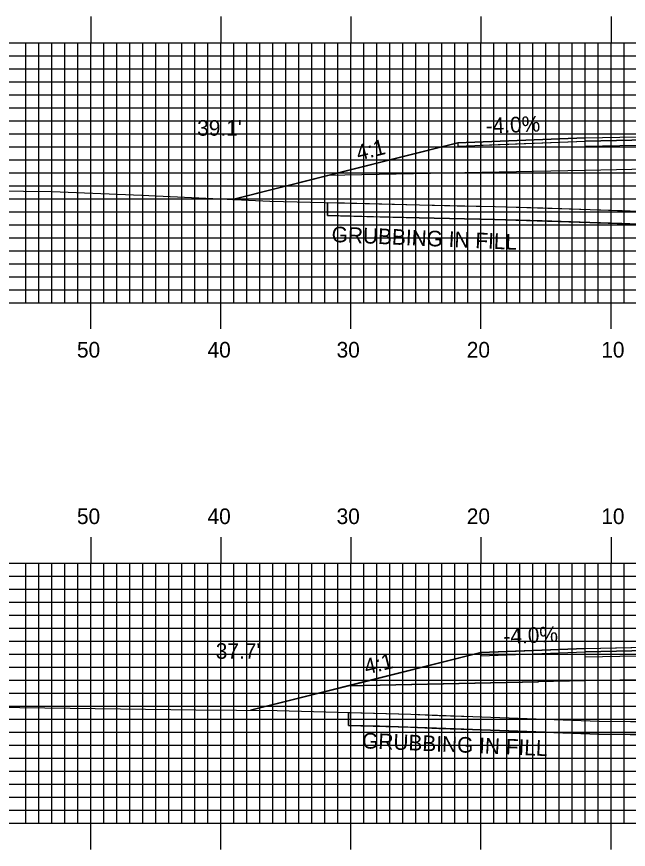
# Model space of a CAD drawing. Extents: x 1773203 to 1773546, y 442591 to 442811.
# Drawn here: x 1773312.9 to 1773360, y 442646.7 to 442710.7 of the extents above; entities that cross this region are included whole.
import ezdxf

# ---------------------------------------------------------------- set-up
doc = ezdxf.new("R2010")
doc.units = 0
for name, color, linetype in [('ANNOTATION', 7, 'Continuous'), ('D_Drainage_Culvert', 7, 'Continuous'), ('D_Roadway_Centerline', 7, 'Continuous'), ('D_Roadway_Edge_Shoulder', 7, 'Continuous'), ('D_Roadway_Edge_TW', 7, 'Continuous'), ('D_Roadway_Pavement', 7, 'Continuous'), ('D_Roadway_SlopeLines', 7, 'Continuous'), ('D_Roadway_SubGrade', 7, 'Continuous'), ('D_Text_Standard', 7, 'Continuous'), ('GRUBBING IN FILL', 7, 'Continuous'), ('H_V ANNOTATION', 7, 'Continuous'), ('MAJOR', 7, 'Continuous'), ('MINOR', 7, 'Continuous'), ('S_Roadway_Centerline', 7, 'Continuous')]:
    doc.layers.add(name, color=color, linetype=linetype)

msp = doc.modelspace()

# ---------------------------------------------------------------- linework, layer by layer
at = {"layer": 'D_Drainage_Culvert'}
for p, q in [((1773356.633, 442701.354), (1773346.862, 442700.963)), ((1773356.633, 442662.104), (1773348.633, 442661.784))]:
    msp.add_line(p, q, dxfattribs=at)
for points in [[(1773346.862, 442700.963), (1773342.862, 442699.963), (1773329.514, 442696.626)], [(1773348.633, 442661.784), (1773344.633, 442660.784), (1773330.914, 442657.355)]]:
    msp.add_lwpolyline(points, dxfattribs=at)
at = {"layer": 'D_Roadway_Centerline'}
for points in [[(1773329.514, 442696.626), (1773346.862, 442700.963), (1773356.633, 442701.354), (1773368.633, 442701.594), (1773380.633, 442701.354), (1773388.632, 442701.034), (1773388.632, 442701.034), (1773412.135, 442695.159)], [(1773330.914, 442657.355), (1773338.457, 442659.24), (1773348.633, 442661.784), (1773348.633, 442661.784), (1773348.633, 442661.784), (1773352.008, 442661.919), (1773356.633, 442662.104), (1773363.648, 442662.245), (1773368.633, 442662.344), (1773380.633, 442662.104), (1773388.632, 442661.784), (1773388.632, 442661.784), (1773412.369, 442655.85)]]:
    msp.add_lwpolyline(points, dxfattribs=at)
at = {"layer": 'D_Roadway_Edge_Shoulder'}
for points in [[(1773356.633, 442701.354), (1773348.633, 442701.034), (1773348.633, 442700.784), (1773356.633, 442701.104)], [(1773356.633, 442662.104), (1773348.633, 442661.784), (1773348.633, 442661.534), (1773356.633, 442661.854)]]:
    msp.add_lwpolyline(points, close=True, dxfattribs=at)
at = {"layer": 'D_Roadway_Edge_TW'}
for points in [[(1773356.633, 442701.104), (1773356.633, 442701.354), (1773368.633, 442701.594), (1773380.633, 442701.354), (1773380.633, 442701.104), (1773368.633, 442701.344)], [(1773356.633, 442661.854), (1773356.633, 442662.104), (1773368.633, 442662.344), (1773380.633, 442662.104), (1773380.633, 442661.854), (1773368.633, 442662.094)]]:
    msp.add_lwpolyline(points, close=True, dxfattribs=at)
at = {"layer": 'D_Roadway_Pavement'}
for points in [[(1773356.633, 442700.687), (1773356.633, 442701.104), (1773368.633, 442701.344), (1773380.633, 442701.104), (1773380.633, 442700.687), (1773368.633, 442700.927)], [(1773356.633, 442661.437), (1773356.633, 442661.854), (1773368.633, 442662.094), (1773380.633, 442661.854), (1773380.633, 442661.437), (1773368.633, 442661.677)]]:
    msp.add_lwpolyline(points, close=True, dxfattribs=at)
at = {"layer": 'D_Roadway_SlopeLines'}
msp.add_lwpolyline([(1773338.457, 442659.24), (1773353.069, 442659.533), (1773338.457, 442659.24), (1773332.659, 442657.791)], dxfattribs=at)
at = {"layer": 'D_Roadway_SubGrade'}
for points in [[(1773356.633, 442698.854), (1773336.84, 442698.458), (1773346.862, 442700.963), (1773346.862, 442700.713), (1773356.633, 442701.104), (1773368.633, 442701.344), (1773380.633, 442701.104), (1773388.632, 442700.784), (1773388.632, 442700.784), (1773388.632, 442701.034), (1773398.808, 442698.49), (1773380.633, 442698.854), (1773368.633, 442699.094)], [(1773356.633, 442659.604), (1773338.457, 442659.24), (1773348.633, 442661.784), (1773348.633, 442661.534), (1773356.633, 442661.854), (1773368.633, 442662.094), (1773380.633, 442661.854), (1773388.633, 442661.534), (1773388.632, 442661.784), (1773398.809, 442659.24), (1773380.633, 442659.604), (1773368.633, 442659.844)]]:
    msp.add_lwpolyline(points, close=True, dxfattribs=at)
at = {"layer": 'GRUBBING IN FILL'}
for p, q in [((1773336.84, 442696.38), (1773336.84, 442695.38)), ((1773336.84, 442696.38), (1773336.84, 442695.38)), ((1773338.457, 442657.187), (1773338.457, 442656.187)), ((1773338.457, 442657.187), (1773338.457, 442656.187))]:
    msp.add_line(p, q, dxfattribs=at)
for points in [[(1773336.84, 442696.38), (1773338.148, 442696.348), (1773343.893, 442696.205), (1773346.807, 442696.136), (1773349.72, 442696.067), (1773353.379, 442695.962), (1773357.037, 442695.858), (1773359.487, 442695.766), (1773361.937, 442695.674), (1773366.151, 442695.682), (1773368.633, 442695.672), (1773368.633, 442694.672), (1773366.15, 442694.682), (1773364.034, 442694.678), (1773361.919, 442694.674), (1773359.462, 442694.766), (1773357.004, 442694.858), (1773353.349, 442694.963), (1773349.694, 442695.067), (1773343.869, 442695.206), (1773340.355, 442695.293), (1773336.84, 442695.38)], [(1773336.84, 442696.38), (1773338.148, 442696.348), (1773343.893, 442696.205), (1773346.807, 442696.136), (1773349.72, 442696.067), (1773353.379, 442695.962), (1773357.037, 442695.858), (1773359.487, 442695.766), (1773361.937, 442695.674), (1773366.151, 442695.682), (1773368.633, 442695.672), (1773368.633, 442694.672), (1773366.15, 442694.682), (1773364.034, 442694.678), (1773361.919, 442694.674), (1773359.462, 442694.766), (1773357.004, 442694.858), (1773353.349, 442694.963), (1773349.694, 442695.067), (1773343.869, 442695.206), (1773340.355, 442695.293), (1773336.84, 442695.38)], [(1773338.457, 442657.187), (1773343.237, 442657.056), (1773348.011, 442656.876), (1773352.869, 442656.7), (1773357.726, 442656.524), (1773361.346, 442656.483), (1773364.965, 442656.443), (1773368.633, 442656.382), (1773368.633, 442655.382), (1773364.952, 442655.443), (1773361.327, 442655.483), (1773357.703, 442655.524), (1773352.84, 442655.7), (1773347.977, 442655.877), (1773346.684, 442655.918), (1773340.829, 442656.122), (1773338.457, 442656.187)], [(1773338.457, 442657.187), (1773343.237, 442657.056), (1773348.011, 442656.876), (1773352.869, 442656.7), (1773357.726, 442656.524), (1773361.346, 442656.483), (1773364.965, 442656.443), (1773368.633, 442656.382), (1773368.633, 442655.382), (1773364.952, 442655.443), (1773361.327, 442655.483), (1773357.703, 442655.524), (1773352.84, 442655.7), (1773347.977, 442655.877), (1773346.684, 442655.918), (1773340.829, 442656.122), (1773338.457, 442656.187)]]:
    msp.add_lwpolyline(points, close=True, dxfattribs=at)
for points in [[(1773336.84, 442695.38), (1773343.869, 442695.206), (1773349.694, 442695.067), (1773357.004, 442694.858), (1773361.919, 442694.674), (1773366.15, 442694.682), (1773378.829, 442694.632), (1773388.378, 442694.435), (1773397.112, 442694.25), (1773406.041, 442694.277), (1773410.276, 442694.204), (1773413.419, 442694.127)], [(1773336.84, 442695.38), (1773343.869, 442695.206), (1773349.694, 442695.067), (1773357.004, 442694.858), (1773361.919, 442694.674), (1773366.15, 442694.682), (1773378.829, 442694.632), (1773388.378, 442694.435), (1773397.112, 442694.25), (1773406.041, 442694.277), (1773410.276, 442694.204), (1773413.419, 442694.127)], [(1773338.457, 442656.187), (1773343.201, 442656.057), (1773345.391, 442655.959), (1773347.977, 442655.877), (1773357.703, 442655.524), (1773364.952, 442655.443), (1773375.185, 442655.273), (1773387.506, 442655.088), (1773393.213, 442655.117), (1773400.869, 442654.965), (1773408.571, 442654.87), (1773413.42, 442654.845)], [(1773338.457, 442656.187), (1773343.201, 442656.057), (1773345.391, 442655.959), (1773347.977, 442655.877), (1773357.703, 442655.524), (1773364.952, 442655.443), (1773375.185, 442655.273), (1773387.506, 442655.088), (1773393.213, 442655.117), (1773400.869, 442654.965), (1773408.571, 442654.87), (1773413.42, 442654.845)]]:
    msp.add_lwpolyline(points, dxfattribs=at)
at = {"layer": 'MAJOR'}
for p, q in [((1773318.633, 442710.669), (1773318.633, 442708.665)), ((1773328.633, 442710.669), (1773328.633, 442708.665)), ((1773338.633, 442710.669), (1773338.633, 442708.665)), ((1773348.633, 442710.669), (1773348.633, 442708.665)), ((1773358.633, 442710.669), (1773358.633, 442708.665)), ((1773228.633, 442708.665), (1773508.633, 442708.665)), ((1773228.633, 442708.665), (1773508.633, 442708.665)), ((1773318.633, 442688.665), (1773318.633, 442708.665)), ((1773328.633, 442688.665), (1773328.633, 442708.665)), ((1773338.633, 442688.665), (1773338.633, 442708.665)), ((1773348.633, 442688.665), (1773348.633, 442708.665)), ((1773358.633, 442688.665), (1773358.633, 442708.665)), ((1773228.633, 442703.665), (1773508.633, 442703.665)), ((1773228.633, 442698.665), (1773508.633, 442698.665)), ((1773228.633, 442693.665), (1773508.633, 442693.665)), ((1773228.633, 442688.665), (1773508.633, 442688.665)), ((1773228.633, 442688.665), (1773508.633, 442688.665)), ((1773318.633, 442686.661), (1773318.633, 442688.665)), ((1773328.633, 442686.661), (1773328.633, 442688.665)), ((1773338.633, 442686.661), (1773338.633, 442688.665)), ((1773348.633, 442686.661), (1773348.633, 442688.665)), ((1773358.633, 442686.661), (1773358.633, 442688.665)), ((1773318.633, 442670.669), (1773318.633, 442668.665)), ((1773328.633, 442670.669), (1773328.633, 442668.665)), ((1773338.633, 442670.669), (1773338.633, 442668.665)), ((1773348.633, 442670.669), (1773348.633, 442668.665)), ((1773358.633, 442670.669), (1773358.633, 442668.665)), ((1773228.633, 442668.665), (1773508.633, 442668.665)), ((1773228.633, 442668.665), (1773508.633, 442668.665)), ((1773318.633, 442648.665), (1773318.633, 442668.665)), ((1773328.633, 442648.665), (1773328.633, 442668.665)), ((1773338.633, 442648.665), (1773338.633, 442668.665)), ((1773348.633, 442648.665), (1773348.633, 442668.665)), ((1773358.633, 442648.665), (1773358.633, 442668.665)), ((1773228.633, 442663.665), (1773508.633, 442663.665)), ((1773228.633, 442658.665), (1773508.633, 442658.665)), ((1773228.633, 442653.665), (1773508.633, 442653.665)), ((1773228.633, 442648.665), (1773508.633, 442648.665)), ((1773228.633, 442648.665), (1773508.633, 442648.665)), ((1773318.633, 442646.661), (1773318.633, 442648.665)), ((1773328.633, 442646.661), (1773328.633, 442648.665)), ((1773338.633, 442646.661), (1773338.633, 442648.665)), ((1773348.633, 442646.661), (1773348.633, 442648.665)), ((1773358.633, 442646.661), (1773358.633, 442648.665))]:
    msp.add_line(p, q, dxfattribs=at)
at = {"layer": 'MINOR'}
for p, q in [((1773313.633, 442688.665), (1773313.633, 442708.665)), ((1773314.633, 442688.665), (1773314.633, 442708.665)), ((1773315.633, 442688.665), (1773315.633, 442708.665)), ((1773316.633, 442688.665), (1773316.633, 442708.665)), ((1773317.633, 442688.665), (1773317.633, 442708.665)), ((1773319.633, 442688.665), (1773319.633, 442708.665)), ((1773320.633, 442688.665), (1773320.633, 442708.665)), ((1773321.633, 442688.665), (1773321.633, 442708.665)), ((1773322.633, 442688.665), (1773322.633, 442708.665)), ((1773323.633, 442688.665), (1773323.633, 442708.665)), ((1773324.633, 442688.665), (1773324.633, 442708.665)), ((1773325.633, 442688.665), (1773325.633, 442708.665)), ((1773326.633, 442688.665), (1773326.633, 442708.665)), ((1773327.633, 442688.665), (1773327.633, 442708.665)), ((1773329.633, 442688.665), (1773329.633, 442708.665)), ((1773330.633, 442688.665), (1773330.633, 442708.665)), ((1773331.633, 442688.665), (1773331.633, 442708.665)), ((1773332.633, 442688.665), (1773332.633, 442708.665)), ((1773333.633, 442688.665), (1773333.633, 442708.665)), ((1773334.633, 442688.665), (1773334.633, 442708.665)), ((1773335.633, 442688.665), (1773335.633, 442708.665)), ((1773336.633, 442688.665), (1773336.633, 442708.665)), ((1773337.633, 442688.665), (1773337.633, 442708.665)), ((1773339.633, 442688.665), (1773339.633, 442708.665)), ((1773340.633, 442688.665), (1773340.633, 442708.665)), ((1773341.633, 442688.665), (1773341.633, 442708.665)), ((1773342.633, 442688.665), (1773342.633, 442708.665)), ((1773343.633, 442688.665), (1773343.633, 442708.665)), ((1773344.633, 442688.665), (1773344.633, 442708.665)), ((1773345.633, 442688.665), (1773345.633, 442708.665)), ((1773346.633, 442688.665), (1773346.633, 442708.665)), ((1773347.633, 442688.665), (1773347.633, 442708.665)), ((1773349.633, 442688.665), (1773349.633, 442708.665)), ((1773350.633, 442688.665), (1773350.633, 442708.665)), ((1773351.633, 442688.665), (1773351.633, 442708.665)), ((1773352.633, 442688.665), (1773352.633, 442708.665)), ((1773353.633, 442688.665), (1773353.633, 442708.665)), ((1773354.633, 442688.665), (1773354.633, 442708.665)), ((1773355.633, 442688.665), (1773355.633, 442708.665)), ((1773356.633, 442688.665), (1773356.633, 442708.665)), ((1773357.633, 442688.665), (1773357.633, 442708.665)), ((1773359.633, 442688.665), (1773359.633, 442708.665)), ((1773228.633, 442707.665), (1773508.633, 442707.665)), ((1773228.633, 442706.665), (1773508.633, 442706.665)), ((1773228.633, 442705.665), (1773508.633, 442705.665)), ((1773228.633, 442704.665), (1773508.633, 442704.665)), ((1773228.633, 442702.665), (1773508.633, 442702.665)), ((1773228.633, 442701.665), (1773508.633, 442701.665)), ((1773228.633, 442700.665), (1773508.633, 442700.665)), ((1773228.633, 442699.665), (1773508.633, 442699.665)), ((1773228.633, 442697.665), (1773508.633, 442697.665)), ((1773228.633, 442696.665), (1773508.633, 442696.665)), ((1773228.633, 442695.665), (1773508.633, 442695.665)), ((1773228.633, 442694.665), (1773508.633, 442694.665)), ((1773228.633, 442692.665), (1773508.633, 442692.665)), ((1773228.633, 442691.665), (1773508.633, 442691.665)), ((1773228.633, 442690.665), (1773508.633, 442690.665)), ((1773228.633, 442689.665), (1773508.633, 442689.665)), ((1773313.633, 442648.665), (1773313.633, 442668.665)), ((1773314.633, 442648.665), (1773314.633, 442668.665)), ((1773315.633, 442648.665), (1773315.633, 442668.665)), ((1773316.633, 442648.665), (1773316.633, 442668.665)), ((1773317.633, 442648.665), (1773317.633, 442668.665)), ((1773319.633, 442648.665), (1773319.633, 442668.665)), ((1773320.633, 442648.665), (1773320.633, 442668.665)), ((1773321.633, 442648.665), (1773321.633, 442668.665)), ((1773322.633, 442648.665), (1773322.633, 442668.665)), ((1773323.633, 442648.665), (1773323.633, 442668.665)), ((1773324.633, 442648.665), (1773324.633, 442668.665)), ((1773325.633, 442648.665), (1773325.633, 442668.665)), ((1773326.633, 442648.665), (1773326.633, 442668.665)), ((1773327.633, 442648.665), (1773327.633, 442668.665)), ((1773329.633, 442648.665), (1773329.633, 442668.665)), ((1773330.633, 442648.665), (1773330.633, 442668.665)), ((1773331.633, 442648.665), (1773331.633, 442668.665)), ((1773332.633, 442648.665), (1773332.633, 442668.665)), ((1773333.633, 442648.665), (1773333.633, 442668.665)), ((1773334.633, 442648.665), (1773334.633, 442668.665)), ((1773335.633, 442648.665), (1773335.633, 442668.665)), ((1773336.633, 442648.665), (1773336.633, 442668.665)), ((1773337.633, 442648.665), (1773337.633, 442668.665)), ((1773339.633, 442648.665), (1773339.633, 442668.665)), ((1773340.633, 442648.665), (1773340.633, 442668.665)), ((1773341.633, 442648.665), (1773341.633, 442668.665)), ((1773342.633, 442648.665), (1773342.633, 442668.665)), ((1773343.633, 442648.665), (1773343.633, 442668.665)), ((1773344.633, 442648.665), (1773344.633, 442668.665)), ((1773345.633, 442648.665), (1773345.633, 442668.665)), ((1773346.633, 442648.665), (1773346.633, 442668.665)), ((1773347.633, 442648.665), (1773347.633, 442668.665)), ((1773349.633, 442648.665), (1773349.633, 442668.665)), ((1773350.633, 442648.665), (1773350.633, 442668.665)), ((1773351.633, 442648.665), (1773351.633, 442668.665)), ((1773352.633, 442648.665), (1773352.633, 442668.665)), ((1773353.633, 442648.665), (1773353.633, 442668.665)), ((1773354.633, 442648.665), (1773354.633, 442668.665)), ((1773355.633, 442648.665), (1773355.633, 442668.665)), ((1773356.633, 442648.665), (1773356.633, 442668.665)), ((1773357.633, 442648.665), (1773357.633, 442668.665)), ((1773359.633, 442648.665), (1773359.633, 442668.665)), ((1773228.633, 442667.665), (1773508.633, 442667.665)), ((1773228.633, 442666.665), (1773508.633, 442666.665)), ((1773228.633, 442665.665), (1773508.633, 442665.665)), ((1773228.633, 442664.665), (1773508.633, 442664.665)), ((1773228.633, 442662.665), (1773508.633, 442662.665)), ((1773228.633, 442661.665), (1773508.633, 442661.665)), ((1773228.633, 442660.665), (1773508.633, 442660.665)), ((1773228.633, 442659.665), (1773508.633, 442659.665)), ((1773228.633, 442657.665), (1773508.633, 442657.665)), ((1773228.633, 442656.665), (1773508.633, 442656.665)), ((1773228.633, 442655.665), (1773508.633, 442655.665)), ((1773228.633, 442654.665), (1773508.633, 442654.665)), ((1773228.633, 442652.665), (1773508.633, 442652.665)), ((1773228.633, 442651.665), (1773508.633, 442651.665)), ((1773228.633, 442650.665), (1773508.633, 442650.665)), ((1773228.633, 442649.665), (1773508.633, 442649.665))]:
    msp.add_line(p, q, dxfattribs=at)
at = {"layer": 'S_Roadway_Centerline'}
for points in [[(1773306.911, 442697.34), (1773315.627, 442697.227), (1773322.548, 442696.953), (1773332.403, 442696.491), (1773343.893, 442696.205), (1773349.72, 442696.067), (1773357.037, 442695.858), (1773361.937, 442695.674), (1773366.151, 442695.682), (1773378.841, 442695.632), (1773388.399, 442695.435), (1773397.121, 442695.25), (1773406.048, 442695.277), (1773410.297, 442695.204), (1773420.484, 442694.953), (1773431.77, 442695.051)], [(1773308.945, 442657.68), (1773313.177, 442657.559), (1773326.715, 442657.389), (1773332.969, 442657.338), (1773343.237, 442657.056), (1773345.429, 442656.958), (1773348.011, 442656.876), (1773357.726, 442656.524), (1773364.965, 442656.443), (1773375.201, 442656.273), (1773387.511, 442656.088), (1773393.22, 442656.117), (1773400.886, 442655.965), (1773408.579, 442655.87), (1773415.52, 442655.834), (1773424.52, 442655.74)]]:
    msp.add_lwpolyline(points, dxfattribs=at)

# ---------------------------------------------------------------- texts
at = {"layer": 'ANNOTATION'}
for s, rotation, p in [('-4.0%', 2.29068, (1773349.017, 442701.677)), ('4:1', 14.04254, (1773339.21, 442699.588)), ('-4.0%', 2.29057, (1773350.383, 442662.443)), ('4:1', 14.04273, (1773339.819, 442660.082))]:
    msp.add_text(s, height=1.2, rotation=rotation, dxfattribs=at).set_placement(p)
at = {"layer": 'D_Text_Standard'}
for s, p in [("39.1'", (1773326.807, 442701.518)), ("37.7'", (1773328.237, 442661.306))]:
    msp.add_text(s, height=1.2, dxfattribs=at).set_placement(p)
at = {"layer": 'GRUBBING IN FILL'}
for p in [(1773337.13, 442693.349), (1773339.47, 442654.431)]:
    msp.add_text('GRUBBING IN FILL', height=1.2, rotation=357.57187, dxfattribs=at).set_placement(p)
at = {"layer": 'H_V ANNOTATION'}
for s, p in [('50', (1773317.562, 442684.465)), ('40', (1773327.605, 442684.465)), ('30', (1773337.53, 442684.465)), ('20', (1773347.541, 442684.465)), ('10', (1773357.884, 442684.465)), ('50', (1773317.562, 442671.665)), ('40', (1773327.605, 442671.665)), ('30', (1773337.53, 442671.665)), ('20', (1773347.541, 442671.665)), ('10', (1773357.884, 442671.665))]:
    msp.add_text(s, height=1.2, dxfattribs=at).set_placement(p)

doc.saveas('drawing.dxf')
